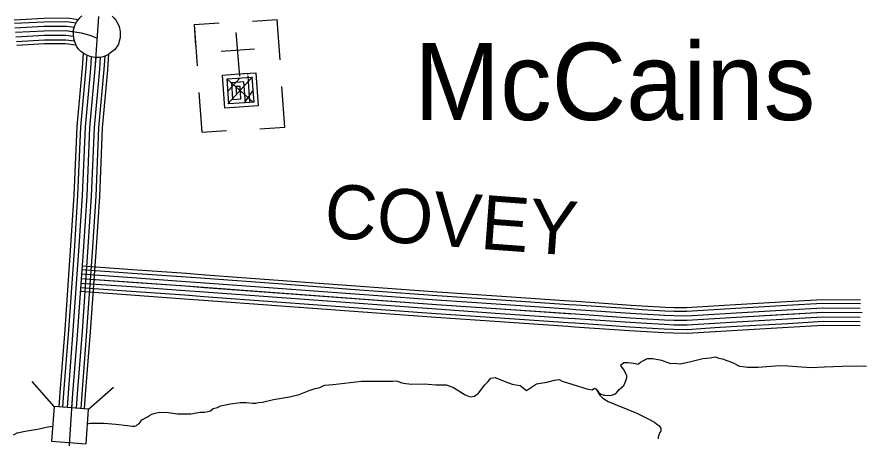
# Model space of a CAD drawing. Extents: x 1551132 to 1791609, y 378168 to 563823.
# Drawn here: x 1653929 to 1659703, y 430159 to 433041 of the extents above; entities that cross this region are included whole.
import ezdxf

# ---------------------------------------------------------------- set-up
doc = ezdxf.new("R2010")
doc.units = 0
for name, color, linetype in [('DESIGN - ROW - Right-of-Way and Easement Labels', 7, 'Continuous'), ('DESIGN - TRANSPORTATION - Text', 7, 'Continuous'), ('DESIGN - UTILITIES - Cable (Underground) with Text', 7, 'Continuous'), ('SURVEY - CENTERLINE - Preliminary Text', 7, 'Continuous'), ('SURVEY - CONTOURS - Index with Text', 7, 'Continuous'), ('SURVEY - DRAINAGE - Storm Sewer', 7, 'Continuous'), ('SURVEY - VEGETATION - Features with Text', 7, 'Continuous')]:
    doc.layers.add(name, color=color, linetype=linetype)

msp = doc.modelspace()

# ---------------------------------------------------------------- linework, layer by layer
at = {"layer": 'DESIGN - TRANSPORTATION - Text'}
for points in [[(1657831.728, 430496.55), (1657869.152, 430490.317), (1657877.185, 430496.275), (1657885.202, 430500.226), (1657893.168, 430496.159), (1657907.068, 430484.05), (1657914.968, 430471.975), (1657926.868, 430459.875), (1657952.784, 430451.683), (1657994.741, 430451.391), (1658020.774, 430459.225), (1658034.832, 430469.142), (1658052.973, 430491.042), (1658085.139, 430518.859), (1658095.28, 430538.818), (1658101.414, 430558.811), (1658105.497, 430570.794), (1658105.614, 430586.82), (1658081.964, 430631.046), (1658074.048, 430641.113), (1658068.123, 430651.171), (1658064.206, 430661.213), (1658068.214, 430663.188), (1658086.297, 430677.08), (1658112.272, 430676.905), (1658132.23, 430674.764), (1658154.196, 430672.605), (1658184.103, 430664.388), (1658188.128, 430668.363), (1658200.195, 430678.297), (1658224.269, 430692.147), (1658232.286, 430696.098), (1658246.335, 430704.006), (1658256.327, 430703.939), (1658284.293, 430703.748), (1658344.158, 430693.314), (1658405.915, 430668.855), (1658429.906, 430670.689), (1658471.83, 430666.389), (1658535.87, 430679.964), (1658625.951, 430703.373), (1658675.942, 430709.031), (1658711.949, 430714.79), (1658733.866, 430706.631), (1658761.807, 430702.431), (1658789.689, 430690.223), (1658829.547, 430675.922), (1658877.32, 430651.555), (1658899.287, 430649.397), (1658933.202, 430643.155), (1659005.142, 430644.655), (1659153.072, 430655.647), (1659209.004, 430653.255), (1659300.861, 430646.605), (1659366.767, 430642.147), (1659458.698, 430645.514), (1659582.612, 430650.655), (1659678.535, 430653.997), (1659746.45, 430651.522)], [(1654412.792, 430255.426), (1654427.983, 430260.067), (1654527.889, 430261.376), (1654605.762, 430254.826), (1654687.602, 430244.242), (1654721.543, 430240), (1654737.526, 430239.892), (1654747.559, 430245.826), (1654755.592, 430251.784), (1654769.65, 430261.701), (1654783.8, 430283.635), (1654823.915, 430305.386), (1654837.957, 430313.294), (1654854.015, 430323.203), (1654876.039, 430329.053), (1654906.063, 430336.861), (1654963.987, 430334.453), (1655027.86, 430325.994), (1655119.767, 430325.361), (1655183.79, 430336.928), (1655215.756, 430336.712), (1655235.764, 430340.578), (1655253.789, 430346.462), (1655273.88, 430362.346), (1655301.896, 430368.154), (1655323.962, 430380.021), (1655391.994, 430393.571), (1655458, 430403.122), (1655499.949, 430402.83), (1655541.882, 430398.538), (1655565.856, 430398.372), (1655583.864, 430402.247), (1655611.847, 430404.055), (1655685.92, 430423.572), (1655795.934, 430440.831), (1655861.999, 430458.398), (1655930.114, 430483.966), (1655972.172, 430497.691), (1656004.196, 430505.483), (1656036.287, 430521.275), (1656094.252, 430524.884), (1656288.239, 430549.568), (1656446.069, 430548.476), (1656502.018, 430548.084), (1656520.009, 430549.959), (1656535.975, 430547.851), (1656565.875, 430537.626), (1656591.799, 430531.434), (1656633.731, 430527.142), (1656717.671, 430530.559), (1656797.544, 430524.001), (1656841.501, 430523.692), (1656857.484, 430523.584), (1656869.467, 430523.501), (1656881.425, 430519.409), (1656919.283, 430505.125), (1656998.831, 430454.499), (1657032.714, 430442.249), (1657062.713, 430446.049), (1657090.829, 430465.883), (1657133.203, 430523.667), (1657153.327, 430543.56), (1657165.419, 430557.493), (1657173.502, 430569.452), (1657187.502, 430571.36), (1657203.501, 430573.252), (1657277.216, 430544.701), (1657321.057, 430528.376), (1657344.998, 430524.201), (1657374.939, 430519.984), (1657418.63, 430483.633), (1657486.911, 430531.226), (1657558.91, 430540.743), (1657610.967, 430556.402), (1657642.966, 430560.185), (1657662.857, 430548.027), (1657728.639, 430527.543), (1657831.728, 430496.55)], [(1657899.643, 430486.7), (1657917.918, 430454.124), (1657941.726, 430431.924), (1657977.533, 430409.648), (1658174.753, 430330.163), (1658256.36, 430287.537), (1658296.176, 430267.228), (1658312.067, 430255.103), (1658323.983, 430245.002), (1658337.833, 430226.885), (1658337.708, 430208.86), (1658331.625, 430196.885), (1658321.417, 430166.909), (1658321.308, 430152.892)], [(1653905.178, 430180.323), (1653931.336, 430194.024), (1653985.427, 430205.374), (1654081.558, 430222.208), (1654129.665, 430233.633), (1654173.947, 430240.792)]]:
    msp.add_lwpolyline(points, dxfattribs=at)
at = {"layer": 'DESIGN - UTILITIES - Cable (Underground) with Text'}
for p, q in [((1655143.124, 432988.064), (1655313.761, 432999.991)), ((1655143.124, 432988.064), (1655153.068, 432845.811)), ((1655541.599, 433011.654), (1655712.277, 433023.581)), ((1655731.682, 432746.768), (1655712.277, 433023.581)), ((1655144.883, 432962.496), (1655162.795, 432706.766)), ((1655556.119, 432819.416), (1655328.547, 432803.479)), ((1655175.649, 432522.621), (1655194.62, 432251.399)), ((1655763.764, 432286.959), (1655744.36, 432565.264)), ((1655593.136, 432275.031), (1655763.764, 432286.959)), ((1655194.62, 432251.399), (1655365.298, 432263.369))]:
    msp.add_line(p, q, dxfattribs=at)
for points in [[(1655429.264, 432934.734), (1655452.636, 432636.319)], [(1655451.177, 432655.286), (1655451.536, 432651.02), (1655565.321, 432658.988), (1655581.208, 432431.409), (1655353.679, 432415.522), (1655337.742, 432643.051), (1655508.428, 432654.979), (1655508.954, 432647.195)], [(1655509.654, 432637.245), (1655522.332, 432455.875), (1655380.121, 432445.931), (1655368.193, 432616.609), (1655538.829, 432628.537), (1655550.799, 432457.901), (1655493.906, 432453.9), (1655483.962, 432596.111), (1655398.644, 432590.168), (1655406.562, 432476.382), (1655463.455, 432480.341), (1655457.52, 432565.701), (1655429.045, 432563.676), (1655433.054, 432506.825)], [(1655543.013, 432630.871), (1655373.562, 432445.889)], [(1655367.884, 432615.509), (1655545.741, 432459.484)], [(1655455.578, 432621.669), (1655375.019, 432535.649)], [(1655543.539, 432535.077), (1655485.856, 432453.716)]]:
    msp.add_lwpolyline(points, dxfattribs=at)
at = {"layer": 'SURVEY - CENTERLINE - Preliminary Text'}
for points in [[(1654488.266, 433043.624), (1654463.583, 432685.398), (1654426.592, 432285.204), (1654407.101, 431816.825), (1654384.51, 431470.591), (1654344.193, 430892.234), (1654310.986, 430463.989), (1654286.361, 430111.763), (1654266.103, 429809.572), (1654243.77, 429497.381), (1654229.495, 429193.139), (1654222.004, 428992.967), (1654232.795, 428830.713), (1654258.928, 428578.257), (1654307.468, 428111.411), (1654352.442, 427702.65), (1654408.657, 427191.695), (1654452.38, 426883.054), (1654496.146, 426580.421), (1654526.495, 426357.965)], [(1654383.052, 432792.692), (1654376.144, 432692.448), (1654339.044, 432291.071), (1654319.503, 431821.508), (1654296.995, 431476.499), (1654256.712, 430898.676), (1654223.504, 430470.44), (1654216.621, 430371.962)], [(1654407.851, 432778.417), (1654401.785, 432690.381), (1654364.71, 432289.346), (1654345.186, 431820.133), (1654322.653, 431474.766), (1654282.362, 430896.784), (1654249.154, 430468.548), (1654242.279, 430370.17)], [(1654438.176, 432767.55), (1654432.684, 432687.889), (1654395.651, 432287.279), (1654376.143, 431818.475), (1654353.577, 431472.674), (1654313.278, 430894.509), (1654280.07, 430466.273), (1654273.203, 430368.012)], [(1654468.95, 432763.283), (1654463.583, 432685.398), (1654426.592, 432285.204), (1654407.101, 431816.825), (1654384.51, 431470.591), (1654344.193, 430892.234), (1654310.986, 430463.989), (1654304.127, 430365.845)], [(1654500.099, 432764.358), (1654494.483, 432682.906), (1654457.533, 432283.129), (1654438.058, 431815.175), (1654415.442, 431468.507), (1654375.109, 430889.959), (1654341.902, 430461.706), (1654335.052, 430363.687)], [(1654531.757, 432772.883), (1654525.382, 432680.414), (1654488.474, 432281.062), (1654469.016, 431813.517), (1654446.366, 431466.416), (1654406.025, 430887.684), (1654372.818, 430459.431), (1654365.976, 430361.528)], [(1654557.448, 432786.15), (1654550.023, 432678.423), (1654513.14, 432279.404), (1654493.699, 431812.2), (1654471.024, 431464.749), (1654430.675, 430885.867), (1654397.467, 430457.614), (1654390.634, 430359.812)]]:
    msp.add_lwpolyline(points, dxfattribs=at)
at = {"layer": 'SURVEY - CONTOURS - Index with Text'}
for points in [[(1653910.338, 433021.765), (1654112.775, 433032.773), (1654273.421, 433033.79), (1654350.228, 433022.698)], [(1653912.88, 432997.147), (1654113.517, 433008.064), (1654271.721, 433009.056), (1654334.937, 432999.931)], [(1653916.063, 432966.28), (1654114.458, 432977.063), (1654269.588, 432978.047), (1654323.303, 432970.288)], [(1653919.246, 432935.404), (1654115.4, 432946.071), (1654267.463, 432947.029), (1654369.394, 432932.312), (1654429.293, 432915.887), (1654478.108, 432896.212)], [(1653919.246, 432935.404), (1654115.4, 432946.071), (1654267.463, 432947.029), (1654316.845, 432939.896)], [(1653922.429, 432904.528), (1654116.342, 432915.079), (1654265.338, 432916.012), (1654316.77, 432908.587)], [(1653925.613, 432873.661), (1654117.283, 432884.078), (1654263.205, 432885.003), (1654322.895, 432876.378)], [(1653928.254, 432848.043), (1654118.058, 432858.369), (1654261.438, 432859.269), (1654333.52, 432848.869)], [(1654719.785, 431285.961), (1654373.46, 431310.67)], [(1654721.552, 431310.62), (1654375.226, 431335.329)], [(1655220.423, 431274.736), (1655089.868, 431284.345), (1654721.527, 431310.62)], [(1659717.684, 431015.348), (1659447.832, 431017.932), (1658855.771, 430983.539), (1658517.721, 430962.738), (1658427.773, 430963.605), (1658363.824, 430966.213), (1658130.071, 430980.472), (1657754.497, 431006.089), (1656803.569, 431071.257), (1655083.601, 431197.851), (1654369.051, 431248.827)], [(1654715.377, 431224.118), (1654369.051, 431248.827)], [(1654717.585, 431255.044), (1654371.26, 431279.752)], [(1655216.332, 431219.168), (1655085.843, 431228.768), (1654717.568, 431255.044)], [(1655218.607, 431250.085), (1655088.085, 431259.694), (1654719.768, 431285.961)], [(1655717.228, 431213.385), (1655218.59, 431250.085)], [(1655719.045, 431238.035), (1655220.406, 431274.736)], [(1654710.968, 431162.275), (1654364.643, 431186.983)], [(1654713.168, 431193.192), (1654366.843, 431217.901)], [(1655211.782, 431157.333), (1655081.36, 431166.933), (1654713.152, 431193.192)], [(1655214.057, 431188.251), (1655083.601, 431197.851), (1654715.36, 431224.118)], [(1655712.678, 431151.55), (1655214.04, 431188.251)], [(1655714.953, 431182.467), (1655216.315, 431219.168)], [(1656213.583, 431145.767), (1655714.937, 431182.467)], [(1656215.858, 431176.684), (1655717.211, 431213.385)], [(1656217.675, 431201.335), (1655719.028, 431238.035)], [(1656716.296, 431164.634), (1656217.658, 431201.335)], [(1654709.135, 431136.624), (1654362.81, 431161.333)], [(1655207.623, 431100.765), (1655077.26, 431110.365), (1654709.118, 431136.624)], [(1655209.507, 431126.416), (1655079.118, 431136.007), (1654710.952, 431162.275)], [(1655708.128, 431089.715), (1655209.49, 431126.416)], [(1655710.403, 431120.632), (1655211.765, 431157.333)], [(1656211.308, 431114.849), (1655712.662, 431151.55)], [(1656712.205, 431109.066), (1656213.566, 431145.767)], [(1656714.48, 431139.983), (1656215.841, 431176.684)], [(1657212.935, 431105.349), (1656807.961, 431133.1), (1656714.463, 431139.983)], [(1657214.626, 431130.008), (1656809.719, 431157.759), (1656716.28, 431164.634)], [(1657713.423, 431095.833), (1657214.601, 431130.017)], [(1655706.237, 431064.064), (1655207.598, 431100.765)], [(1656206.758, 431053.014), (1655708.112, 431089.715)], [(1656209.033, 431083.932), (1655710.387, 431120.632)], [(1656707.655, 431047.231), (1656209.017, 431083.932)], [(1656709.93, 431078.148), (1656211.292, 431114.849)], [(1657208.693, 431043.489), (1656803.569, 431071.257), (1656709.913, 431078.148)], [(1657210.81, 431074.415), (1656805.769, 431102.182), (1656712.188, 431109.066)], [(1657709.615, 431040.24), (1657210.793, 431074.424)], [(1657711.74, 431071.174), (1657212.918, 431105.358)], [(1658210.12, 431037.706), (1658134.071, 431042.348), (1657758.73, 431067.949), (1657711.723, 431071.174)], [(1658211.62, 431062.382), (1658135.663, 431067.007), (1657760.414, 431092.608), (1657713.415, 431095.833)], [(1659199.688, 431090.375), (1658850.596, 431070.099), (1658700.266, 431060.849)], [(1659201.121, 431065.699), (1658852.071, 431045.432), (1658701.783, 431036.182)], [(1659705.093, 431102.192), (1659445.732, 431104.676), (1659199.663, 431090.375)], [(1659704.851, 431077.475), (1659446.332, 431079.95), (1659201.105, 431065.699)], [(1656204.867, 431027.363), (1655706.22, 431064.064)], [(1656703.488, 430990.663), (1656204.85, 431027.363)], [(1656705.38, 431016.313), (1656206.742, 431053.014)], [(1657204.451, 430981.629), (1656799.178, 431009.413), (1656705.363, 431016.313)], [(1657206.576, 431012.564), (1656801.369, 431040.331), (1656707.638, 431047.231)], [(1657705.381, 430978.388), (1657206.56, 431012.572)], [(1657707.498, 431009.314), (1657208.676, 431043.498)], [(1658206.345, 430975.822), (1658130.071, 430980.472), (1657754.497, 431006.089), (1657707.481, 431009.314)], [(1658208.228, 431006.764), (1658132.071, 431011.406), (1657756.614, 431037.015), (1657709.606, 431040.24)], [(1658701.8, 431036.182), (1658516.112, 431024.756), (1658429.331, 431025.598), (1658366.974, 431028.14), (1658210.103, 431037.706)], [(1658700.283, 431060.849), (1658515.471, 431049.482), (1658429.956, 431050.307), (1658368.233, 431052.824), (1658211.611, 431062.382)], [(1659202.913, 431034.757), (1658853.921, 431014.481), (1658703.691, 431005.239)], [(1659704.56, 431046.474), (1659447.082, 431048.941), (1659202.896, 431034.757)], [(1659704.26, 431015.473), (1659447.832, 431017.932), (1659204.696, 431003.806)], [(1657202.693, 430955.979), (1656797.353, 430983.754), (1656703.48, 430990.663)], [(1657701.498, 430921.803), (1657202.677, 430955.987)], [(1657703.256, 430947.454), (1657204.435, 430981.638)], [(1658204.461, 430944.879), (1658128.072, 430949.537), (1657752.38, 430975.163), (1657705.356, 430978.388)], [(1658705.608, 430974.297), (1658517.721, 430962.738), (1658427.773, 430963.605), (1658363.824, 430966.213), (1658206.328, 430975.822)], [(1658703.708, 431005.239), (1658516.921, 430993.747), (1658428.556, 430994.597), (1658365.399, 430997.172), (1658208.22, 431006.764)], [(1659204.713, 431003.806), (1658855.771, 430983.539), (1658705.591, 430974.297)], [(1659206.513, 430972.855), (1658857.621, 430952.596), (1658707.491, 430943.354)], [(1659703.96, 430984.473), (1659448.582, 430986.922), (1659206.496, 430972.855)], [(1659703.668, 430953.472), (1659449.332, 430955.913), (1659208.288, 430941.913)], [(1658201.003, 430888.269), (1658124.422, 430892.936), (1657748.514, 430918.578), (1657701.481, 430921.803)], [(1658202.57, 430913.937), (1658126.072, 430918.595), (1657750.264, 430944.229), (1657703.24, 430947.454)], [(1658709.416, 430912.412), (1658519.329, 430900.72), (1658426.214, 430901.611), (1658360.674, 430904.286), (1658202.553, 430913.937)], [(1658707.508, 430943.354), (1658518.521, 430931.729), (1658426.989, 430932.612), (1658362.249, 430935.254), (1658204.436, 430944.879)], [(1659208.305, 430941.913), (1658859.471, 430921.645), (1658709.4, 430912.412)], [(1659209.796, 430916.237), (1658861.004, 430895.978), (1658710.983, 430886.744)], [(1659703.418, 430927.754), (1659449.957, 430930.188), (1659209.779, 430916.237)], [(1658710.991, 430886.744), (1658519.996, 430874.994), (1658425.564, 430875.902), (1658359.366, 430878.602), (1658200.986, 430888.269)]]:
    msp.add_lwpolyline(points, dxfattribs=at)
at = {"layer": 'SURVEY - DRAINAGE - Storm Sewer'}
for p, q in [((1654183.316, 430374.289), (1654034.311, 430545.703)), ((1654420.342, 430357.729), (1654591.755, 430506.733))]:
    msp.add_line(p, q, dxfattribs=at)
msp.add_lwpolyline([(1654166.755, 430137.264), (1654403.773, 430120.694), (1654420.342, 430357.729), (1654183.316, 430374.289)], close=True, dxfattribs=at)
at = {"layer": 'SURVEY - VEGETATION - Features with Text'}
msp.add_lwpolyline([(1654580.897, 433046.357), (1654595.289, 433032.599), (1654606.547, 433017.798), (1654615.997, 433001.839), (1654625.488, 432985.839), (1654632.113, 432965.155), (1654636.588, 432937.971), (1654637.254, 432918.796), (1654635.579, 432897.337), (1654630.038, 432874.469), (1654624.496, 432854.336), (1654612.388, 432835.418), (1654597.597, 432816.276), (1654580.122, 432801.092), (1654558.656, 432785.417), (1654538.857, 432774.958), (1654519.49, 432768.558), (1654498.483, 432763.9), (1654465.883, 432762.983), (1654437.184, 432767.925), (1654411.685, 432777.075), (1654387.518, 432789.525), (1654367.261, 432804.842), (1654351.394, 432820.451), (1654337.878, 432840.585), (1654325.478, 432870.569), (1654318.129, 432891.803), (1654316.57, 432925.079), (1654317.237, 432951.513), (1654326.612, 432982.972), (1654337.336, 433004.831), (1654350.169, 433023.115), (1654360.886, 433034.14), (1654374.686, 433047.432)], dxfattribs=at)

# ---------------------------------------------------------------- texts
at = {"layer": 'DESIGN - ROW - Right-of-Way and Easement Labels'}
msp.add_text('COVEY', height=369.9914, rotation=355.79185, dxfattribs=at).set_placement((1656026.363, 431533.26))
at = {"layer": 'SURVEY - VEGETATION - Features with Text'}
msp.add_text('McCains', height=527.9876, rotation=0.0000306, dxfattribs=at).set_placement((1656650.057, 432335.34))

doc.saveas('drawing.dxf')
